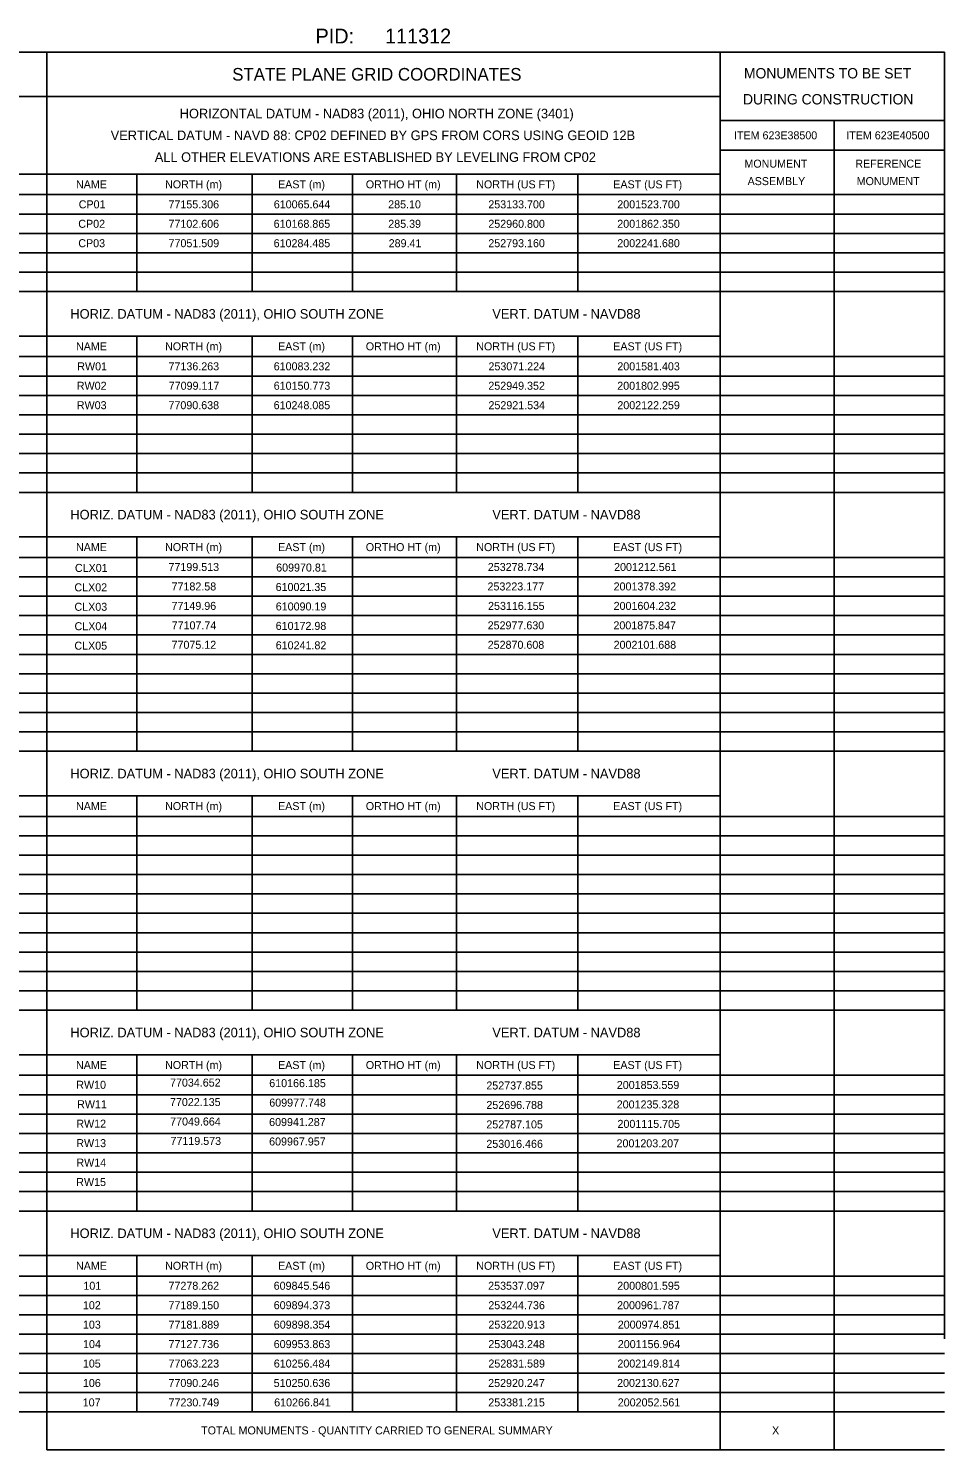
# Model space of a CAD drawing. Extents: x -4451 to 6119, y -1533 to 848.
# Drawn here: x 392.9 to 640.1, y 464.2 to 848.1 of the extents above; entities that cross this region are included whole.
import ezdxf

# ---------------------------------------------------------------- set-up
doc = ezdxf.new("R2010")
doc.units = 0
doc.layers.add('SC_Scratch1', color=7, linetype='Continuous')

msp = doc.modelspace()

# ---------------------------------------------------------------- linework, layer by layer
at = {"layer": 'SC_Scratch1'}
for p, q in [((30.12, 841.7), (640.12, 841.7)), ((397.85, 464.37), (397.85, 841.7)), ((579.55, 464.57), (579.55, 841.7)), ((640.12, 494.32), (640.12, 841.7)), ((246.43, 829.69), (397.85, 829.69)), ((397.85, 829.69), (579.55, 829.69)), ((579.55, 823.22), (640.12, 823.22)), ((610.38, 777.03), (610.38, 823.22)), ((579.55, 815.21), (640.12, 815.21)), ((30.12, 808.75), (579.55, 808.75)), ((422.19, 777.03), (422.19, 808.75)), ((453.28, 777.03), (453.28, 808.75)), ((480.32, 777.03), (480.32, 808.75)), ((508.44, 777.03), (508.44, 808.75)), ((541.16, 777.03), (541.16, 808.75)), ((246.43, 803.2), (640.12, 803.2)), ((30.12, 797.97), (640.12, 797.97)), ((30.12, 792.73), (640.12, 792.73)), ((30.12, 787.5), (640.12, 787.5)), ((30.12, 782.26), (640.12, 782.26)), ((30.12, 777.03), (640.12, 777.03)), ((610.38, 733.31), (610.38, 777.03)), ((30.12, 765.02), (579.55, 765.02)), ((422.19, 722.78), (422.19, 765.02)), ((453.28, 722.81), (453.28, 765.02)), ((480.32, 722.83), (480.32, 765.02)), ((508.44, 722.8), (508.44, 765.02)), ((541.16, 722.8), (541.16, 765.02)), ((30.12, 759.47), (640.12, 759.47)), ((30.12, 754.24), (640.12, 754.24)), ((30.12, 749), (640.12, 749)), ((30.12, 743.77), (640.12, 743.77)), ((30.12, 738.53), (640.12, 738.53)), ((30.12, 733.3), (640.12, 733.3)), ((610.38, 689.59), (610.38, 733.31)), ((610.38, 670.5), (610.38, 733.31)), ((30.12, 728.06), (640.12, 728.06)), ((30.12, 722.83), (640.12, 722.83)), ((30.12, 722.83), (640.12, 722.83)), ((610.38, 679.11), (610.38, 722.83)), ((30.12, 710.82), (579.55, 710.82)), ((422.19, 652.96), (422.19, 710.82)), ((453.28, 652.96), (453.28, 710.82)), ((480.32, 653.05), (480.32, 710.82)), ((508.44, 653.05), (508.44, 710.82)), ((541.16, 652.96), (541.16, 710.82)), ((30.12, 705.27), (640.12, 705.27)), ((30.12, 700.04), (640.12, 700.04)), ((30.12, 694.8), (640.12, 694.8)), ((30.12, 689.57), (640.12, 689.57)), ((30.12, 684.33), (640.12, 684.33)), ((30.12, 679.1), (640.12, 679.1)), ((610.38, 652.91), (610.38, 679.11)), ((30.12, 673.86), (640.12, 673.86)), ((30.12, 668.63), (640.12, 668.63)), ((30.12, 663.39), (640.12, 663.39)), ((30.12, 658.16), (640.12, 658.16)), ((30.12, 652.92), (640.12, 652.92)), ((30.12, 652.92), (640.12, 652.92)), ((30.12, 652.92), (640.12, 652.92)), ((610.38, 609.21), (610.38, 652.92)), ((30.12, 640.91), (579.55, 640.91)), ((422.19, 583.06), (422.19, 640.91)), ((453.28, 583.06), (453.28, 640.91)), ((480.32, 583.14), (480.32, 640.91)), ((508.44, 583.14), (508.44, 640.91)), ((541.16, 583.05), (541.16, 640.91)), ((30.12, 635.37), (640.12, 635.37)), ((30.12, 630.14), (640.12, 630.14)), ((30.12, 624.9), (640.12, 624.9)), ((30.12, 619.67), (640.12, 619.67)), ((30.12, 614.43), (640.12, 614.43)), ((30.12, 609.2), (640.12, 609.2)), ((610.38, 583.01), (610.38, 609.21)), ((30.12, 603.96), (640.12, 603.96)), ((30.12, 598.73), (640.12, 598.73)), ((30.12, 593.49), (640.12, 593.49)), ((30.12, 588.25), (640.12, 588.25)), ((30.12, 583.02), (640.12, 583.02)), ((30.12, 583.02), (640.12, 583.02)), ((610.38, 528.73), (610.38, 583.02)), ((30.12, 571.01), (579.55, 571.01)), ((422.19, 528.78), (422.19, 571.01)), ((453.28, 528.81), (453.28, 571.01)), ((480.32, 528.82), (480.32, 571.01)), ((508.44, 528.8), (508.44, 571.01)), ((541.16, 528.8), (541.16, 571.01)), ((30.12, 565.47), (640.12, 565.47)), ((30.12, 560.23), (640.12, 560.23)), ((30.12, 555), (640.12, 555)), ((30.12, 549.76), (640.12, 549.76)), ((30.12, 544.53), (640.12, 544.53)), ((30.12, 539.29), (640.12, 539.29)), ((30.12, 534.06), (640.12, 534.06)), ((30.12, 528.82), (640.12, 528.82)), ((30.12, 528.82), (640.12, 528.82)), ((30.12, 528.82), (640.12, 528.82)), ((610.38, 464.16), (610.38, 528.82)), ((30.12, 516.81), (579.55, 516.81)), ((422.19, 474.58), (422.19, 516.81)), ((453.28, 474.61), (453.28, 516.81)), ((480.32, 474.62), (480.32, 516.81)), ((508.44, 474.6), (508.44, 516.81)), ((541.16, 474.6), (541.16, 516.81)), ((30.12, 511.27), (640.12, 511.27)), ((30.12, 506.03), (640.12, 506.03)), ((30.12, 500.8), (640.12, 500.8)), ((30.12, 495.56), (640.12, 495.56)), ((30.12, 490.33), (640.12, 490.33)), ((30.12, 485.09), (640.12, 485.09)), ((30.12, 479.86), (640.12, 479.86)), ((30.12, 474.62), (640.12, 474.62)), ((30.12, 474.62), (640.12, 474.62)), ((397.85, 464.37), (640.12, 464.37))]:
    msp.add_line(p, q, dxfattribs=at)

# ---------------------------------------------------------------- texts
for s, height, p in [('PID:', 4, (470.38, 844.01)), ('111312', 4, (489.13, 844.01)), ('STATE PLANE GRID COORDINATES', 3.4, (447.9, 833.99)), ('MONUMENTS TO BE SET', 2.8, (585.99, 834.57)), ('DURING CONSTRUCTION', 2.8, (585.74, 827.55)), ('HORIZONTAL DATUM - NAD83 (2011), OHIO NORTH ZONE (3401)', 2.5878, (433.73, 823.8)), ('VERTICAL DATUM - NAVD 88: CP02 DEFINED BY GPS FROM CORS USING GEOID 12B', 2.5878, (415.1, 817.92)), ('ITEM 623E38500', 2.1565, (583.32, 818.14)), ('ITEM 623E40500', 2.1565, (613.6, 818.14)), ('ALL OTHER ELEVATIONS ARE ESTABLISHED BY LEVELING FROM CP02', 2.5878, (427, 812.04)), ('MONUMENT ', 2.157, (586.12, 810.49)), ('REFERENCE', 2.157, (616.04, 810.49)), ('NAME', 2.157, (405.75, 804.9)), ('NORTH (m)', 2.157, (429.78, 804.9)), ('EAST (m)', 2.157, (460.27, 804.9)), ('ORTHO HT (m)', 2.1565, (483.95, 804.9)), ('NORTH (US FT)', 2.1565, (513.75, 804.9)), ('EAST (US FT)', 2.1565, (550.73, 804.9)), ('ASSEMBLY', 2.157, (586.97, 805.77)), ('MONUMENT', 2.157, (616.41, 805.77)), ('CP01', 2.16, (406.48, 799.5)), ('77155.306', 2.16, (430.7, 799.5)), ('610065.644', 2.16, (459.12, 799.5)), ('285.10', 2.16, (489.99, 799.5)), ('253133.700', 2.16, (517.01, 799.5)), ('2001523.700', 2.16, (551.81, 799.5)), ('CP02', 2.16, (406.36, 794.25)), ('77102.606', 2.16, (430.7, 794.25)), ('610168.865', 2.16, (459.08, 794.25)), ('285.39', 2.16, (490.01, 794.25)), ('252960.800', 2.16, (517.01, 794.25)), ('2001862.350', 2.16, (551.81, 794.25)), ('CP03', 2.16, (406.36, 789.01)), ('77051.509', 2.16, (430.72, 789.01)), ('610284.485', 2.16, (459.08, 789.01)), ('289.41', 2.16, (490.12, 789.01)), ('252793.160', 2.16, (517.01, 789.01)), ('2002241.680', 2.16, (551.81, 789.01)), ('HORIZ. DATUM - NAD83 (2011), OHIO SOUTH ZONE', 2.5878, (404.22, 769.72)), ('VERT. DATUM - NAVD88', 2.5878, (518.09, 769.72)), ('NAME', 2.157, (405.75, 761.17)), ('NORTH (m)', 2.157, (429.78, 761.17)), ('EAST (m)', 2.157, (460.27, 761.17)), ('ORTHO HT (m)', 2.1565, (483.95, 761.17)), ('NORTH (US FT)', 2.1565, (513.75, 761.17)), ('EAST (US FT)', 2.1565, (550.73, 761.17)), ('RW01', 2.16, (406.09, 755.77)), ('77136.263', 2.16, (430.71, 755.77)), ('610083.232', 2.16, (459.1, 755.77)), ('253071.224', 2.16, (517.05, 755.77)), ('2001581.403', 2.16, (551.82, 755.77)), ('RW02', 2.16, (405.97, 750.53)), ('77099.117', 2.16, (430.77, 750.53)), ('610150.773', 2.16, (459.1, 750.53)), ('252949.352', 2.16, (517.02, 750.53)), ('2001802.995', 2.16, (551.8, 750.53)), ('RW03', 2.16, (405.97, 745.28)), ('77090.638', 2.16, (430.7, 745.28)), ('610248.085', 2.16, (459.08, 745.28)), ('252921.534', 2.16, (517.05, 745.28)), ('2002122.259', 2.16, (551.83, 745.28)), ('HORIZ. DATUM - NAD83 (2011), OHIO SOUTH ZONE', 2.5878, (404.22, 715.52)), ('VERT. DATUM - NAVD88', 2.5878, (518.09, 715.52)), ('NAME', 2.157, (405.75, 706.97)), ('NORTH (m)', 2.157, (429.78, 706.97)), ('EAST (m)', 2.157, (460.27, 706.97)), ('ORTHO HT (m)', 2.1565, (483.95, 706.97)), ('NORTH (US FT)', 2.1565, (513.75, 706.97)), ('EAST (US FT)', 2.1565, (550.73, 706.97)), ('CLX01', 2.16, (405.45, 701.35)), ('77199.513', 2.16, (430.7, 701.6)), ('609970.81', 2.16, (459.76, 701.45)), ('253278.734', 2.16, (516.87, 701.6)), ('2001212.561', 2.16, (550.95, 701.6)), ('CLX02', 2.16, (405.32, 696.11)), ('77182.58', 2.16, (431.53, 696.35)), ('610021.35', 2.16, (459.62, 696.2)), ('253223.177', 2.16, (516.79, 696.35)), ('2001378.392', 2.16, (550.82, 696.35)), ('CLX03', 2.16, (405.33, 690.86)), ('77149.96', 2.16, (431.52, 691.1)), ('610090.19', 2.16, (459.65, 690.95)), ('253116.155', 2.16, (516.94, 691.1)), ('2001604.232', 2.16, (550.82, 691.1)), ('CLX04', 2.16, (405.35, 685.61)), ('77107.74', 2.16, (431.56, 685.85)), ('610172.98', 2.16, (459.63, 685.7)), ('252977.630', 2.16, (516.83, 685.85)), ('2001875.847', 2.16, (550.77, 685.85)), ('CLX05', 2.16, (405.31, 680.36)), ('77075.12', 2.16, (431.53, 680.6)), ('610241.82', 2.16, (459.64, 680.46)), ('252870.608', 2.16, (516.84, 680.6)), ('2002101.688', 2.16, (550.82, 680.6)), ('HORIZ. DATUM - NAD83 (2011), OHIO SOUTH ZONE', 2.5878, (404.22, 645.62)), ('VERT. DATUM - NAVD88', 2.5878, (518.09, 645.62)), ('NAME', 2.157, (405.75, 637.06)), ('NORTH (m)', 2.157, (429.78, 637.06)), ('EAST (m)', 2.157, (460.27, 637.06)), ('ORTHO HT (m)', 2.1565, (483.95, 637.06)), ('NORTH (US FT)', 2.1565, (513.75, 637.06)), ('EAST (US FT)', 2.1565, (550.73, 637.06)), ('HORIZ. DATUM - NAD83 (2011), OHIO SOUTH ZONE', 2.5878, (404.22, 575.72)), ('VERT. DATUM - NAVD88', 2.5878, (518.09, 575.72)), ('NAME', 2.157, (405.75, 567.16)), ('NORTH (m)', 2.157, (429.78, 567.16)), ('EAST (m)', 2.157, (460.27, 567.16)), ('ORTHO HT (m)', 2.1565, (483.95, 567.16)), ('NORTH (US FT)', 2.1565, (513.75, 567.16)), ('EAST (US FT)', 2.1565, (550.73, 567.16)), ('77034.652', 2.16, (431.12, 562.41)), ('610166.185', 2.16, (457.89, 562.26)), ('RW10', 2.16, (405.82, 561.82)), ('252737.855', 2.16, (516.48, 561.63)), ('2001853.559', 2.16, (551.68, 561.77)), ('RW11', 2.16, (406.06, 556.57)), ('77022.135', 2.16, (431.11, 557.16)), ('609977.748', 2.16, (457.9, 557.01)), ('252696.788', 2.16, (516.49, 556.38)), ('2001235.328', 2.16, (551.66, 556.52)), ('RW12', 2.16, (405.83, 551.32)), ('77049.664', 2.16, (431.15, 551.91)), ('609941.287', 2.16, (457.86, 551.76)), ('252787.105', 2.16, (516.48, 551.13)), ('2001115.705', 2.16, (551.87, 551.27)), ('RW13', 2.16, (405.83, 546.07)), ('77119.573', 2.16, (431.24, 546.66)), ('609967.957', 2.16, (457.86, 546.52)), ('253016.466', 2.16, (516.48, 545.88)), ('2001203.207', 2.16, (551.61, 546.02)), ('RW14', 2.16, (405.85, 540.82)), ('RW15', 2.16, (405.81, 535.57)), ('HORIZ. DATUM - NAD83 (2011), OHIO SOUTH ZONE', 2.5878, (404.22, 521.52)), ('VERT. DATUM - NAVD88', 2.5878, (518.09, 521.52)), ('NAME', 2.157, (405.75, 512.96)), ('NORTH (m)', 2.157, (429.78, 512.96)), ('EAST (m)', 2.157, (460.27, 512.96)), ('ORTHO HT (m)', 2.1565, (483.95, 512.96)), ('NORTH (US FT)', 2.1565, (513.75, 512.96)), ('EAST (US FT)', 2.1565, (550.73, 512.96)), ('101', 2.16, (407.74, 507.57)), ('77278.262', 2.16, (430.71, 507.57)), ('609845.546', 2.16, (459.09, 507.57)), ('253537.097', 2.16, (516.97, 507.57)), ('2000801.595', 2.16, (551.8, 507.57)), ('102', 2.16, (407.61, 502.32)), ('77189.150', 2.16, (430.7, 502.32)), ('609894.373', 2.16, (459.1, 502.32)), ('253244.736', 2.16, (517.01, 502.32)), ('2000961.787', 2.16, (551.76, 502.32)), ('103', 2.16, (407.62, 497.07)), ('77181.889', 2.16, (430.72, 497.07)), ('609898.354', 2.16, (459.12, 497.07)), ('253220.913', 2.16, (517.03, 497.07)), ('2000974.851', 2.16, (551.94, 497.07)), ('104', 2.16, (407.64, 491.82)), ('77127.736', 2.16, (430.7, 491.82)), ('609953.863', 2.16, (459.1, 491.82)), ('253043.248', 2.16, (517.01, 491.82)), ('2001156.964', 2.16, (551.95, 491.82)), ('105', 2.16, (407.6, 486.57)), ('77063.223', 2.16, (430.71, 486.57)), ('610256.484', 2.16, (459.12, 486.57)), ('252831.589', 2.16, (517.03, 486.57)), ('2002149.814', 2.16, (551.84, 486.57)), ('106', 2.16, (407.61, 481.32)), ('77090.246', 2.16, (430.7, 481.32)), ('510250.636', 2.16, (459.09, 481.32)), ('252920.247', 2.16, (516.97, 481.32)), ('2002130.627', 2.16, (551.76, 481.32)), ('107', 2.16, (407.56, 476.08)), ('77230.749', 2.16, (430.72, 476.08)), ('610266.841', 2.16, (459.22, 476.08)), ('253381.215', 2.16, (517, 476.08)), ('2002052.561', 2.16, (551.94, 476.08)), ('TOTAL MONUMENTS - QUANTITY CARRIED TO GENERAL SUMMARY', 2.1565, (439.52, 468.52)), ('X', 2.16, (593.58, 468.52))]:
    msp.add_text(s, height=height, dxfattribs=at).set_placement(p)

doc.saveas('drawing.dxf')
